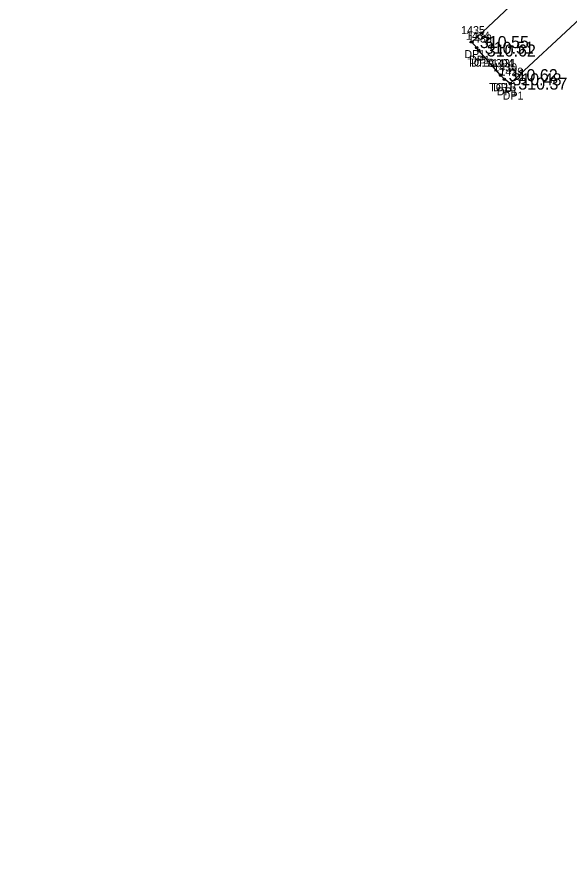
# Model space of a CAD drawing. Extents: x 1970076 to 1971136, y 803126 to 804215.
# Drawn here: x 1970395.7 to 1970464.7, y 803542.4 to 803647.8 of the extents above; entities that cross this region are included whole.
import ezdxf

# ---------------------------------------------------------------- set-up
doc = ezdxf.new("R2010")
doc.units = 0
for name, color, linetype in [('RD_EX_Conc_txCode', 7, 'Continuous'), ('RD_EX_Driveway', 7, 'Continuous'), ('RD_EX_Driveway_txCode', 7, 'Continuous'), ('RD_EX_TX_Conc_ELEV', 7, 'Continuous'), ('RD_EX_TX_Driveway_ELEV', 7, 'Continuous'), ('RD_SMD_Locator', 7, 'Continuous')]:
    doc.layers.add(name, color=color, linetype=linetype)

msp = doc.modelspace()

# ---------------------------------------------------------------- linework, layer by layer
at = {"layer": 'RD_EX_Driveway'}
msp.add_lwpolyline([(1970511.89, 803542.41), (1970514.79, 803545.04), (1970514.01, 803573.46), (1970523.86, 803581.55), (1970466.06, 803647.51), (1970457.37, 803639.42), (1970456.64, 803639.96), (1970456.17, 803640.48), (1970453.44, 803643.56), (1970453.19, 803643.9), (1970452.57, 803644.61), (1970462.07, 803653.54), (1970470.49, 803657.02), (1970478.91, 803655.17), (1970478.91, 803655.17), (1970452.14, 803685.91), (1970452.14, 803685.91), (1970451.19, 803676.84), (1970447.7, 803671.47), (1970440.83, 803665.68), (1970436.4, 803664.89), (1970405.79, 803676.49), (1970395.71, 803667.64)], dxfattribs=at)
at = {"layer": 'RD_SMD_Locator'}
for centre in [(1970452.57, 803644.61), (1970453.19, 803643.9), (1970453.44, 803643.56), (1970453.44, 803643.56), (1970456.17, 803640.48), (1970456.17, 803640.48), (1970456.64, 803639.96), (1970457.37, 803639.42)]:
    msp.add_circle(centre, 0.15, dxfattribs=at)

# ---------------------------------------------------------------- texts
at = {"layer": 'RD_EX_Conc_txCode'}
for s, p in [('1433', (1970452.1, 803644.56)), ('TC1A', (1970452, 803641.56)), ('1394', (1970454.82, 803641.48)), ('TC1B', (1970454.73, 803638.48))]:
    msp.add_text(s, height=1, dxfattribs=at).set_placement(p)
at = {"layer": 'RD_EX_Driveway_txCode'}
for s, p in [('1435', (1970451.23, 803645.61)), ('1434', (1970451.84, 803644.9)), ('1432', (1970452.1, 803644.56)), ('DP1', (1970451.63, 803642.61)), ('DP1', (1970452.24, 803641.9)), ('DP1', (1970452.5, 803641.56)), ('1431', (1970455.1, 803641.48)), ('1430', (1970455.25, 803640.96)), ('1429', (1970456.02, 803640.42)), ('DP1', (1970455.22, 803638.48)), ('DP1', (1970455.69, 803637.96)), ('DP1', (1970456.42, 803637.42))]:
    msp.add_text(s, height=1, dxfattribs=at).set_placement(p)
at = {"layer": 'RD_EX_TX_Conc_ELEV'}
for p in [(1970454.44, 803642.81), (1970457.17, 803639.73)]:
    msp.add_text('310.62', height=1.5, dxfattribs=at).set_placement(p)
at = {"layer": 'RD_EX_TX_Driveway_ELEV'}
for s, p in [('310.55', (1970453.57, 803643.86)), ('310.51', (1970454.19, 803643.15)), ('310.62', (1970454.44, 803642.81)), ('310.62', (1970457.17, 803639.73)), ('310.48', (1970457.64, 803639.21)), ('310.37', (1970458.37, 803638.67))]:
    msp.add_text(s, height=1.5, dxfattribs=at).set_placement(p)

doc.saveas('drawing.dxf')
